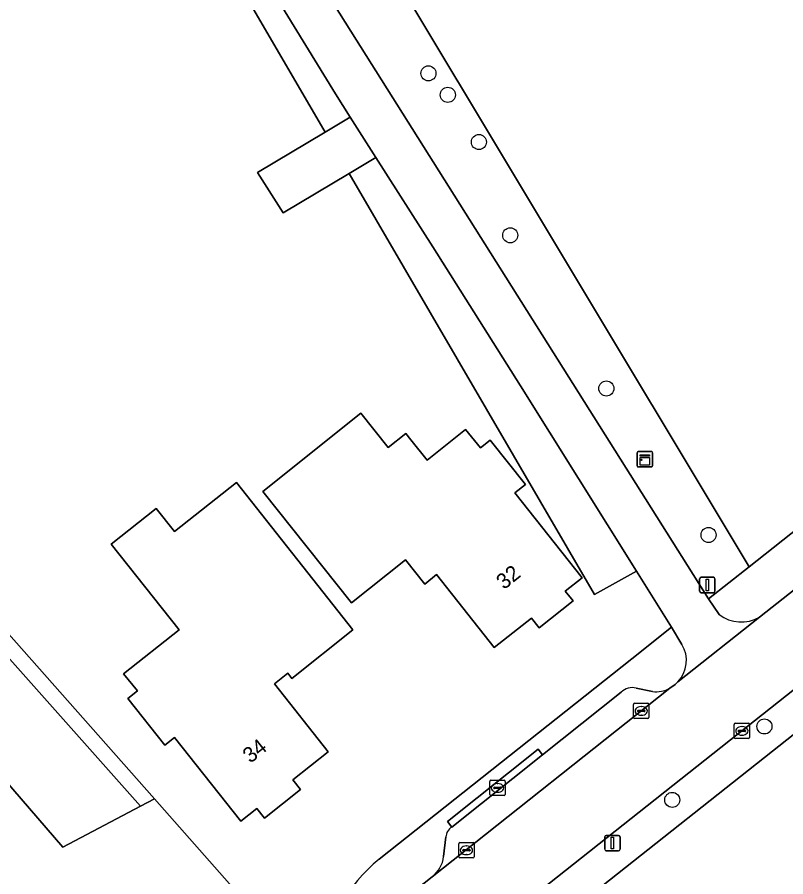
# Model space of a CAD drawing. Extents: x 157320 to 158835, y 386650 to 388491.
# Drawn here: x 157686.5 to 157736.3, y 387412.1 to 387467.9 of the extents above; entities that cross this region are included whole.
import ezdxf

# ---------------------------------------------------------------- set-up
doc = ezdxf.new("R2010")
doc.units = 0
for name, color, linetype in [('IMGEO_Boom', 7, 'Continuous'), ('IMGEO_Brandkraan', 7, 'Continuous'), ('IMGEO_Erf', 7, 'Continuous'), ('IMGEO_Groenvoorziening', 7, 'Continuous'), ('IMGEO_Haag', 7, 'Continuous'), ('IMGEO_Hek', 7, 'Continuous'), ('IMGEO_Kast', 7, 'Continuous'), ('IMGEO_Kolk', 7, 'Continuous'), ('IMGEO_Lichtmast', 7, 'Continuous'), ('IMGEO_Loofbos', 7, 'Continuous'), ('IMGEO_Muur', 7, 'Continuous'), ('IMGEO_Pand', 7, 'Continuous'), ('IMGEO_Pand_nummerreeks', 7, 'Continuous'), ('IMGEO_Parkeervlak_open', 7, 'Continuous'), ('IMGEO_Rijbaan_lokaal_open', 7, 'Continuous'), ('IMGEO_Verkeersbordpaal', 7, 'Continuous'), ('IMGEO_Voetpad_open', 7, 'Continuous')]:
    doc.layers.add(name, color=color, linetype=linetype)

msp = doc.modelspace()

# ---------------------------------------------------------------- linework, layer by layer
at = {"layer": 'IMGEO_Boom'}
for centre in [(157713.162, 387464.215), (157714.418, 387462.822), (157716.434, 387459.764), (157718.468, 387453.718), (157724.701, 387443.788), (157731.329, 387434.288), (157734.952, 387421.877), (157728.976, 387417.113)]:
    msp.add_circle(centre, 0.489, dxfattribs=at)
at = {"layer": 'IMGEO_Brandkraan'}
for p, q in [((157717.14, 387417.463), (157717.14, 387418.315)), ((157717.215, 387418.389), (157718.067, 387418.389)), ((157717.628, 387418.169), (157717.653, 387418.169)), ((157718.141, 387418.315), (157718.141, 387417.463)), ((157717.399, 387417.883), (157717.399, 387417.895)), ((157717.837, 387417.846), (157717.439, 387417.846)), ((157717.442, 387417.932), (157717.84, 387417.932)), ((157717.651, 387417.609), (157717.626, 387417.609)), ((157717.883, 387417.895), (157717.883, 387417.883)), ((157718.067, 387417.389), (157717.215, 387417.389))]:
    msp.add_line(p, q, dxfattribs=at)
for points in [[(157717.14, 387417.463), (157717.14, 387418.315)], [(157717.215, 387418.389), (157718.067, 387418.389)], [(157718.141, 387418.315), (157718.141, 387417.463)], [(157718.067, 387417.389), (157717.215, 387417.389)]]:
    msp.add_lwpolyline(points, dxfattribs=at)
for centre, radius, start, end in [((157717.217, 387418.313), 0.0765, 91.552, 178.448), ((157717.217, 387418.313), 0.0765, 91.552, 178.448), ((157718.065, 387418.313), 0.0765, 1.552, 88.448), ((157718.065, 387418.313), 0.0765, 1.552, 88.448), ((157717.439, 387417.892), 0.0403, 85.8775, 175.7526), ((157717.436, 387417.882), 0.0366, 178.938, 274.7102), ((157717.84, 387417.889), 0.043, 264.8664, 352.4533), ((157717.844, 387417.894), 0.0386, 1.7309, 96.639), ((157717.217, 387417.465), 0.0765, 181.552, 268.448), ((157717.217, 387417.465), 0.0765, 181.552, 268.448), ((157718.065, 387417.465), 0.0765, 271.552, 358.448), ((157718.065, 387417.465), 0.0765, 271.552, 358.448)]:
    msp.add_arc(centre, radius, start, end, dxfattribs=at)
for centre, major_axis, ratio, start_param, end_param in [((157717.627, 387417.889), (-0.387, 0.002), 0.722429, 4.712389, 7.853982), ((157717.652, 387417.889), (-0.39, 0.002), 0.717154, 1.570796, 4.712389)]:
    msp.add_ellipse(centre, major_axis=major_axis, ratio=ratio, start_param=start_param, end_param=end_param, dxfattribs=at)
at = {"layer": 'IMGEO_Erf'}
for points in [[(157708.019, 387457.727), (157703.737, 387455.18), (157702.073, 387457.797), (157706.459, 387460.405), (157701.376, 387469.131), (157700.285, 387471.004), (157700.083, 387470.872), (157690.402, 387485.56), (157691.938, 387486.629), (157686.922, 387494.383), (157686.466, 387495.373)], [(157789.148, 387462.761), (157739.933, 387423.805), (157719.941, 387407.98), (157719.213, 387407.404)], [(157709.959, 387413.279), (157726.347, 387426.266), (157728.937, 387428.318), (157726.666, 387431.937), (157723.924, 387430.425), (157708.019, 387457.727)], [(157677.124, 387437.81), (157695.387, 387417.176), (157705.279, 387406), (157706.235, 387406.552)]]:
    msp.add_lwpolyline(points, dxfattribs=at)
for points in [[(157708.779, 387442.192), (157710.56, 387439.96), (157711.696, 387440.867), (157712.019, 387440.462), (157713.077, 387439.136), (157715.575, 387441.129), (157716.532, 387439.931), (157717.156, 387440.431), (157719.447, 387437.569), (157718.764, 387437.024), (157723.123, 387431.521), (157722.028, 387430.648), (157722.538, 387430.019), (157720.349, 387428.273), (157719.844, 387428.906), (157717.435, 387426.99), (157713.685, 387431.723), (157712.921, 387431.105), (157711.672, 387432.677), (157708.176, 387429.883), (157702.411, 387437.113)], [(157695.506, 387436.007), (157696.687, 387434.512), (157700.705, 387437.687), (157708.256, 387428.133), (157704.299, 387424.99), (157704.032, 387425.326), (157703.179, 387424.637), (157706.657, 387420.241), (157704.367, 387418.419), (157704.87, 387417.784), (157702.532, 387415.931), (157702.025, 387416.558), (157701.002, 387415.745), (157696.684, 387421.157), (157696.061, 387420.654), (157693.667, 387423.684), (157694.295, 387424.18), (157693.391, 387425.29), (157696.988, 387428.133), (157692.586, 387433.7)]]:
    msp.add_lwpolyline(points, close=True, dxfattribs=at)
msp.add_arc((157716.774, 387405.112), 10.637, 129.8427, 172.2204, dxfattribs=at)
at = {"layer": 'IMGEO_Groenvoorziening'}
for points in [[(157696.367, 387490.699), (157695.265, 387492.316), (157694.258, 387491.516), (157704.407, 387475.776), (157705.588, 387473.956), (157704.419, 387472.864), (157731.334, 387430.155), (157733.955, 387432.23), (157708.847, 387474.081)], [(157673.186, 387399.455), (157687.699, 387400.6), (157689.782, 387400.764), (157689.799, 387401.757), (157693.089, 387402.039), (157693.182, 387401.042), (157694.713, 387401.171), (157695.426, 387401.196), (157696.134, 387401.285), (157696.831, 387401.437), (157697.512, 387401.651), (157698.171, 387401.924), (157698.433, 387402.053), (157705.279, 387406), (157695.387, 387417.176), (157694.481, 387416.709), (157689.444, 387414.056), (157669.714, 387436.922)]]:
    msp.add_lwpolyline(points, dxfattribs=at)
for points in [[(157708.092, 387461.377), (157707.128, 387462.88), (157701.935, 387471.356), (157701.611, 387471.872), (157700.285, 387471.004), (157701.376, 387469.131), (157706.459, 387460.405)], [(157672.256, 387443.31), (157671.22, 387444.36), (157658.884, 387438.296), (157636.69, 387465.18), (157635.835, 387464.645), (157634.812, 387464.005), (157634.231, 387463.686), (157633.203, 387463.122), (157653.441, 387428.946), (157661.44, 387432.867), (157669.714, 387436.922), (157689.444, 387414.056), (157694.481, 387416.709), (157676.322, 387437.108), (157677.124, 387437.81)], [(157708.019, 387457.727), (157723.924, 387430.425), (157726.666, 387431.937), (157719.123, 387443.96), (157713.447, 387452.976), (157709.756, 387458.76)], [(157677.124, 387437.81), (157676.322, 387437.108), (157694.481, 387416.709), (157695.387, 387417.176)]]:
    msp.add_lwpolyline(points, close=True, dxfattribs=at)
at = {"layer": 'IMGEO_Haag'}
msp.add_lwpolyline([(157677.124, 387437.81), (157676.322, 387437.108), (157694.481, 387416.709), (157695.387, 387417.176)], close=True, dxfattribs=at)
at = {"layer": 'IMGEO_Hek'}
msp.add_lwpolyline([(157708.711, 387474.308), (157733.955, 387432.23)], dxfattribs=at)
at = {"layer": 'IMGEO_Kast'}
for p, q in [((157726.7, 387438.772), (157726.7, 387439.613)), ((157726.7, 387439.613), (157726.7, 387438.772)), ((157726.775, 387439.697), (157727.616, 387439.697)), ((157727.616, 387439.697), (157726.775, 387439.697)), ((157727.7, 387439.622), (157727.7, 387438.781)), ((157727.7, 387438.781), (157727.7, 387439.622)), ((157727.625, 387438.697), (157726.784, 387438.697)), ((157726.784, 387438.697), (157727.625, 387438.697))]:
    msp.add_line(p, q, dxfattribs=at)
for points in [[(157726.895, 387439.487), (157727.495, 387439.487), (157727.495, 387439.402), (157726.895, 387439.402), (157726.895, 387439.487)], [(157726.895, 387439.312), (157727.495, 387439.312), (157727.495, 387438.823), (157726.895, 387438.823), (157726.895, 387439.312)]]:
    msp.add_lwpolyline(points, dxfattribs=at)
msp.add_circle((157726.979, 387439.161), 0.0377, dxfattribs=at)
for centre, start, end in [((157726.778, 387439.619), 92.4484, 184.2845), ((157726.778, 387439.619), 92.4484, 184.2845), ((157727.622, 387439.619), 2.4484, 94.2845), ((157727.622, 387439.619), 2.4484, 94.2845), ((157726.778, 387438.775), 182.4484, 274.2845), ((157726.778, 387438.775), 182.4484, 274.2845), ((157727.622, 387438.775), 272.4484, 4.2845), ((157727.622, 387438.775), 272.4484, 4.2845)]:
    msp.add_arc(centre, 0.0779, start, end, dxfattribs=at)
at = {"layer": 'IMGEO_Kolk'}
for p, q in [((157726.464, 387422.456), (157726.464, 387423.308)), ((157726.539, 387423.382), (157727.391, 387423.382)), ((157726.952, 387423.162), (157726.977, 387423.162)), ((157727.465, 387423.308), (157727.465, 387422.456)), ((157726.723, 387422.876), (157726.723, 387422.888)), ((157727.161, 387422.839), (157726.763, 387422.839)), ((157726.766, 387422.925), (157727.164, 387422.925)), ((157726.975, 387422.602), (157726.95, 387422.602)), ((157727.207, 387422.888), (157727.207, 387422.876)), ((157727.391, 387422.382), (157726.539, 387422.382)), ((157732.993, 387421.161), (157732.993, 387422.013)), ((157733.068, 387422.087), (157733.92, 387422.087)), ((157733.994, 387422.013), (157733.994, 387421.161)), ((157733.252, 387421.581), (157733.252, 387421.593)), ((157733.69, 387421.544), (157733.292, 387421.544)), ((157733.295, 387421.63), (157733.693, 387421.63)), ((157733.481, 387421.867), (157733.506, 387421.867)), ((157733.736, 387421.593), (157733.736, 387421.581)), ((157733.92, 387421.087), (157733.068, 387421.087)), ((157733.504, 387421.307), (157733.479, 387421.307)), ((157715.125, 387413.422), (157715.125, 387414.274)), ((157715.2, 387414.348), (157716.052, 387414.348)), ((157716.126, 387414.274), (157716.126, 387413.422)), ((157715.384, 387413.842), (157715.384, 387413.854)), ((157715.822, 387413.805), (157715.424, 387413.805)), ((157715.427, 387413.891), (157715.825, 387413.891)), ((157715.613, 387414.128), (157715.638, 387414.128)), ((157715.868, 387413.854), (157715.868, 387413.842)), ((157716.052, 387413.348), (157715.2, 387413.348)), ((157715.636, 387413.568), (157715.611, 387413.568))]:
    msp.add_line(p, q, dxfattribs=at)
for points in [[(157726.464, 387422.456), (157726.464, 387423.308)], [(157726.539, 387423.382), (157727.391, 387423.382)], [(157727.465, 387423.308), (157727.465, 387422.456)], [(157727.391, 387422.382), (157726.539, 387422.382)], [(157732.993, 387421.161), (157732.993, 387422.013)], [(157733.068, 387422.087), (157733.92, 387422.087)], [(157733.994, 387422.013), (157733.994, 387421.161)], [(157733.92, 387421.087), (157733.068, 387421.087)], [(157715.125, 387413.422), (157715.125, 387414.274)], [(157715.2, 387414.348), (157716.052, 387414.348)], [(157716.126, 387414.274), (157716.126, 387413.422)], [(157716.052, 387413.348), (157715.2, 387413.348)]]:
    msp.add_lwpolyline(points, dxfattribs=at)
for centre, radius, start, end in [((157726.541, 387423.306), 0.0765, 91.552, 178.448), ((157726.541, 387423.306), 0.0765, 91.552, 178.448), ((157727.389, 387423.306), 0.0765, 1.552, 88.448), ((157727.389, 387423.306), 0.0765, 1.552, 88.448), ((157726.763, 387422.885), 0.0403, 85.8775, 175.7526), ((157726.76, 387422.875), 0.0366, 178.938, 274.7102), ((157727.164, 387422.882), 0.043, 264.8664, 352.4533), ((157727.168, 387422.887), 0.0386, 1.7309, 96.639), ((157726.541, 387422.458), 0.0765, 181.552, 268.448), ((157726.541, 387422.458), 0.0765, 181.552, 268.448), ((157727.389, 387422.458), 0.0765, 271.552, 358.448), ((157727.389, 387422.458), 0.0765, 271.552, 358.448), ((157733.07, 387422.011), 0.0765, 91.552, 178.448), ((157733.07, 387422.011), 0.0765, 91.552, 178.448), ((157733.918, 387422.011), 0.0765, 1.552, 88.448), ((157733.918, 387422.011), 0.0765, 1.552, 88.448), ((157733.292, 387421.59), 0.0403, 85.8775, 175.7526), ((157733.289, 387421.58), 0.0366, 178.938, 274.7102), ((157733.693, 387421.587), 0.043, 264.8664, 352.4533), ((157733.697, 387421.592), 0.0386, 1.7309, 96.639), ((157733.07, 387421.163), 0.0765, 181.552, 268.448), ((157733.07, 387421.163), 0.0765, 181.552, 268.448), ((157733.918, 387421.163), 0.0765, 271.552, 358.448), ((157733.918, 387421.163), 0.0765, 271.552, 358.448), ((157715.202, 387414.272), 0.0765, 91.552, 178.448), ((157715.202, 387414.272), 0.0765, 91.552, 178.448), ((157716.05, 387414.272), 0.0765, 1.552, 88.448), ((157716.05, 387414.272), 0.0765, 1.552, 88.448), ((157715.424, 387413.851), 0.0403, 85.8775, 175.7526), ((157715.421, 387413.841), 0.0366, 178.938, 274.7102), ((157715.825, 387413.848), 0.043, 264.8664, 352.4533), ((157715.829, 387413.853), 0.0386, 1.7309, 96.639), ((157715.202, 387413.424), 0.0765, 181.552, 268.448), ((157715.202, 387413.424), 0.0765, 181.552, 268.448), ((157716.05, 387413.424), 0.0765, 271.552, 358.448), ((157716.05, 387413.424), 0.0765, 271.552, 358.448)]:
    msp.add_arc(centre, radius, start, end, dxfattribs=at)
for centre, major_axis, ratio, start_param, end_param in [((157726.951, 387422.882), (-0.387, 0.002), 0.722429, 4.712389, 7.853982), ((157726.976, 387422.882), (-0.39, 0.002), 0.717154, 1.570796, 4.712389), ((157733.48, 387421.587), (-0.387, 0.002), 0.722429, 4.712389, 7.853982), ((157733.505, 387421.587), (-0.39, 0.002), 0.717154, 1.570796, 4.712389), ((157715.612, 387413.848), (-0.387, 0.002), 0.722429, 4.712389, 7.853982), ((157715.637, 387413.848), (-0.39, 0.002), 0.717154, 1.570796, 4.712389)]:
    msp.add_ellipse(centre, major_axis=major_axis, ratio=ratio, start_param=start_param, end_param=end_param, dxfattribs=at)
at = {"layer": 'IMGEO_Lichtmast'}
for p, q in [((157724.699, 387414.814), (157725.489, 387414.814)), ((157725.489, 387414.814), (157724.699, 387414.814)), ((157724.599, 387413.914), (157724.599, 387414.714)), ((157724.599, 387414.714), (157724.599, 387413.914)), ((157725.589, 387414.714), (157725.589, 387413.914)), ((157725.589, 387413.914), (157725.589, 387414.714)), ((157725.489, 387413.814), (157724.699, 387413.814)), ((157724.699, 387413.814), (157725.489, 387413.814))]:
    msp.add_line(p, q, dxfattribs=at)
msp.add_lwpolyline([(157725.019, 387414.689), (157725.169, 387414.689), (157725.169, 387413.939), (157725.019, 387413.939), (157725.019, 387414.689)], dxfattribs=at)
for centre, start, end in [((157724.699, 387414.714), 90, 180), ((157724.699, 387414.714), 90, 180), ((157725.489, 387414.714), 0, 90), ((157725.489, 387414.714), 360, 90), ((157724.699, 387413.914), 180, 270), ((157724.699, 387413.914), 180, 270), ((157725.489, 387413.914), 270, 0), ((157725.489, 387413.914), 270, 0)]:
    msp.add_arc(centre, 0.1, start, end, dxfattribs=at)
at = {"layer": 'IMGEO_Loofbos'}
msp.add_lwpolyline([(157708.847, 387474.081), (157733.955, 387432.23), (157780.092, 387468.756)], dxfattribs=at)
at = {"layer": 'IMGEO_Muur'}
for points in [[(157708.092, 387461.377), (157707.128, 387462.88)], [(157709.756, 387458.76), (157713.447, 387452.976)], [(157713.447, 387452.976), (157719.123, 387443.96)], [(157719.941, 387407.98), (157739.933, 387423.805)]]:
    msp.add_lwpolyline(points, dxfattribs=at)
at = {"layer": 'IMGEO_Pand'}
for points in [[(157702.073, 387457.797), (157703.737, 387455.18), (157708.019, 387457.727), (157709.756, 387458.76), (157708.092, 387461.377), (157706.459, 387460.405)], [(157717.435, 387426.99), (157719.844, 387428.906), (157720.349, 387428.273), (157722.538, 387430.019), (157722.028, 387430.648), (157723.123, 387431.521), (157718.764, 387437.024), (157719.447, 387437.569), (157717.156, 387440.431), (157716.532, 387439.931), (157715.575, 387441.129), (157713.077, 387439.136), (157712.019, 387440.462), (157711.696, 387440.867), (157710.56, 387439.96), (157708.779, 387442.192), (157702.411, 387437.113), (157708.176, 387429.883), (157711.672, 387432.677), (157712.921, 387431.105), (157713.685, 387431.723)], [(157701.002, 387415.745), (157702.025, 387416.558), (157702.532, 387415.931), (157704.87, 387417.784), (157704.367, 387418.419), (157706.657, 387420.241), (157703.179, 387424.637), (157704.032, 387425.326), (157704.299, 387424.99), (157708.256, 387428.133), (157700.705, 387437.687), (157696.687, 387434.512), (157695.506, 387436.007), (157692.586, 387433.7), (157696.988, 387428.133), (157693.391, 387425.29), (157694.295, 387424.18), (157693.667, 387423.684), (157696.061, 387420.654), (157696.684, 387421.157)]]:
    msp.add_lwpolyline(points, close=True, dxfattribs=at)
at = {"layer": 'IMGEO_Parkeervlak_open'}
for points in [[(157713.414, 387412.132), (157728.819, 387424.351)], [(157727.694, 387424.141), (157726.64, 387424.364)], [(157725.663, 387424.101), (157720.559, 387420.041), (157714.67, 387415.356)], [(157714.285, 387414.711), (157714.148, 387413.443)]]:
    msp.add_lwpolyline(points, dxfattribs=at)
for centre, radius, start, end in [((157726.388, 387423.353), 1.041, 76.0053, 134.1274), ((157727.941, 387425.937), 1.813, 262.176, 298.9711), ((157715.191, 387414.608), 0.912, 124.8418, 173.4923), ((157712.166, 387413.692), 1.998, 308.67, 352.843)]:
    msp.add_arc(centre, radius, start, end, dxfattribs=at)
at = {"layer": 'IMGEO_Rijbaan_lokaal_open'}
for points in [[(157789.134, 387465.635), (157785.992, 387469.595), (157777.753, 387463.018), (157742.004, 387434.766), (157734.626, 387428.957), (157729.343, 387424.766), (157729.155, 387424.591), (157728.819, 387424.351), (157713.414, 387412.132), (157711.848, 387410.892)], [(157717.797, 387409.175), (157738.571, 387425.62), (157741.55, 387427.969), (157750.551, 387435.1), (157755.274, 387438.843), (157755.697, 387439.178), (157764.498, 387446.189), (157769.289, 387449.931), (157778.663, 387457.339), (157783.382, 387461.072), (157789.134, 387465.635)]]:
    msp.add_lwpolyline(points, dxfattribs=at)
at = {"layer": 'IMGEO_Verkeersbordpaal'}
for p, q in [((157730.751, 387430.645), (157730.751, 387431.445)), ((157730.751, 387431.445), (157730.751, 387430.645)), ((157730.851, 387431.545), (157731.641, 387431.545)), ((157731.641, 387431.545), (157730.851, 387431.545)), ((157731.741, 387431.445), (157731.741, 387430.645)), ((157731.741, 387430.645), (157731.741, 387431.445)), ((157731.641, 387430.545), (157730.851, 387430.545)), ((157730.851, 387430.545), (157731.641, 387430.545))]:
    msp.add_line(p, q, dxfattribs=at)
msp.add_lwpolyline([(157731.171, 387431.42), (157731.321, 387431.42), (157731.321, 387430.67), (157731.171, 387430.67), (157731.171, 387431.42)], dxfattribs=at)
for centre, start, end in [((157730.851, 387431.445), 90, 180), ((157730.851, 387431.445), 90, 180), ((157731.641, 387431.445), 0, 90), ((157731.641, 387431.445), 360, 90), ((157730.851, 387430.645), 180, 270), ((157730.851, 387430.645), 180, 270), ((157731.641, 387430.645), 270, 0), ((157731.641, 387430.645), 270, 0)]:
    msp.add_arc(centre, 0.1, start, end, dxfattribs=at)
at = {"layer": 'IMGEO_Voetpad_open'}
for points in [[(157732.02, 387429.128), (157731.334, 387430.155), (157704.419, 387472.864), (157701.935, 387471.356), (157707.128, 387462.88), (157708.092, 387461.377), (157709.756, 387458.76), (157713.447, 387452.976), (157719.123, 387443.96), (157726.666, 387431.937), (157728.937, 387428.318), (157729.605, 387427.188)], [(157780.092, 387468.756), (157733.955, 387432.23), (157731.334, 387430.155), (157732.02, 387429.128)], [(157792.621, 387462.222), (157789.608, 387466.011), (157789.134, 387465.635), (157783.382, 387461.072), (157783.692, 387460.68), (157778.973, 387456.947), (157778.663, 387457.339), (157769.289, 387449.931), (157769.596, 387449.537), (157764.805, 387445.795), (157764.498, 387446.189), (157755.697, 387439.178), (157755.274, 387438.843), (157755.584, 387438.452), (157750.86, 387434.71), (157750.551, 387435.1), (157741.55, 387427.969), (157741.859, 387427.577), (157738.88, 387425.228), (157738.571, 387425.62), (157717.797, 387409.175)], [(157734.626, 387428.957), (157742.004, 387434.766)], [(157729.343, 387424.766), (157734.626, 387428.957)], [(157729.605, 387427.188), (157728.937, 387428.318), (157726.347, 387426.266), (157709.959, 387413.279)], [(157728.819, 387424.351), (157729.155, 387424.591), (157729.343, 387424.766)], [(157726.64, 387424.364), (157727.694, 387424.141)], [(157714.67, 387415.356), (157714.399, 387415.719), (157720.281, 387420.394), (157720.559, 387420.041), (157725.663, 387424.101)], [(157715.553, 387405.67), (157715.437, 387404.451), (157719.131, 387407.383), (157719.213, 387407.404), (157719.941, 387407.98), (157739.933, 387423.805)], [(157714.148, 387413.443), (157714.285, 387414.711)], [(157711.848, 387410.892), (157713.414, 387412.132)]]:
    msp.add_lwpolyline(points, dxfattribs=at)
msp.add_lwpolyline([(157714.67, 387415.356), (157720.559, 387420.041), (157720.281, 387420.394), (157714.399, 387415.719)], close=True, dxfattribs=at)
for centre, radius, start, end in [((157733.452, 387431.003), 2.359, 232.6367, 299.8549), ((157733.452, 387431.003), 2.359, 232.6367, 299.8549), ((157727.876, 387426.15), 2.017, 316.6727, 30.9793), ((157727.876, 387426.15), 2.017, 316.6727, 30.9793), ((157726.388, 387423.353), 1.041, 76.0053, 134.1274), ((157727.941, 387425.937), 1.813, 262.176, 298.9711), ((157715.191, 387414.608), 0.912, 124.8418, 173.4923), ((157716.774, 387405.112), 10.637, 129.8427, 172.2204), ((157712.166, 387413.692), 1.998, 308.67, 352.843)]:
    msp.add_arc(centre, radius, start, end, dxfattribs=at)

# ---------------------------------------------------------------- texts
at = {"layer": 'IMGEO_Pand_nummerreeks'}
for s, rotation, p in [('32', 38.5429, (157718.061, 387430.711)), ('34', 38.4856, (157701.614, 387419.452))]:
    msp.add_text(s, height=1, rotation=rotation, dxfattribs=at).set_placement(p)

doc.saveas('drawing.dxf')
